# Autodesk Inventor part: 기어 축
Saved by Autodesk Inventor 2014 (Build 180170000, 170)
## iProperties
Created: 2026-04
Part Number: 기어 축
Material: 일반
Document SubType Name: Modeling
Designer: dg
Density: 1 g/cm^3
Appearance: 기본값
Author: dg
Author: jhkim
Creation Date: 2026-03-27
Sending System: Autodesk Inventor 2026
Preprocessor: ST-DEVELOPER v20.1
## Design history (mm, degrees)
node "기어 축1"
node "솔리드1"
node "기준1"
